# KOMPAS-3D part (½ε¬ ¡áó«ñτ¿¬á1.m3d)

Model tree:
1. Эскиз:1
2. Операция выдавливания:1
     Расстояние 1 = 4; Расстояние 2 = 1
3. Эскиз:2
4. Операция выдавливания:2
     Расстояние 1 = 2.5; Расстояние 2 = 2.5
5. Скругление:1
     Радиус = 1.2
6. Эскиз:3
7. Вырезать элемент выдавливания:1
     Расстояние 1 = 28.4433
8. Эскиз:4
9. Операция выдавливания:3
     Расстояние 1 = 1; Расстояние 2 = 2.5
10. Эскиз:5
11. Операция выдавливания:4
     Расстояние 1 = 1.5; Расстояние 2 = 2.5
12. Скругление:2
     Радиус = 0.5
13. Скругление:3
     Радиус = 0.5
14. Эскиз:6
15. Вырезать элемент выдавливания:2
     Расстояние 1 = 0.5
16. Эскиз:7
17. Операция выдавливания:5
     Расстояние 1 = 0.5; Расстояние 2 = 2.5
18. Эскиз:8
19. Операция выдавливания:6
     Расстояние 1 = 0.5; Расстояние 2 = 2.5
20. Скругление:4
     Радиус = 0.5
21. Эскиз:9
22. Операция выдавливания:7
     Расстояние 1 = 0.2; Расстояние 2 = 1.5
23. Скругление:5
     Радиус = 0.2
24. Эскиз:10
25. Вырезать элемент выдавливания:3
     Расстояние 1 = 1
26. Эскиз:11
27. Операция выдавливания:8
     Расстояние 1 = 1.2; Расстояние 2 = 1.5
28. Эскиз:12
29. Вырезать элемент выдавливания:4
     Расстояние 1 = 0.3
30. Эскиз:13
31. Вырезать элемент выдавливания:5
     Расстояние 1 = 0.3
32. Эскиз:14
33. Операция выдавливания:9
     Расстояние 1 = 3
34. Скругление:6
     Радиус = 1
35. Эскиз:15
36. Вырезать элемент выдавливания:6
     Расстояние 1 = 3; Угол 1 = 71
37. Эскиз:16
38. Вырезать элемент выдавливания:7
     Расстояние 1 = 0.5
39. Эскиз:17
40. Вырезать элемент выдавливания:8
     Расстояние 1 = 0.1
41. Скругление:8
     Радиус = 0.5
42. Скругление:9
     Радиус = 0.3
43. Скругление:10
     Радиус = 0.3
44. Скругление:11
     Радиус = 0.3
45. Скругление:12
     Радиус = 0.3
46. Скругление:13
     Радиус = 0.3
47. Скругление:14
     Радиус = 0.3
48. Скругление:15
     Радиус = 0.3
49. Эскиз:18
50. Операция выдавливания:10
     Расстояние 1 = 1
51. Эскиз:19
52. Операция выдавливания:11
     Расстояние 1 = 0.3; Расстояние 2 = 0.3
53. Ломаная:1
54. Перпендикулярная плоскость:1
55. Эскиз:20
56. Кинематическая операция:1
     Толщина стенки 1 = 1; Толщина стенки 2 = 1

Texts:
  люк наводчика1
  Сплав АЛ8  ГОСТ 1583-93
  stalker61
